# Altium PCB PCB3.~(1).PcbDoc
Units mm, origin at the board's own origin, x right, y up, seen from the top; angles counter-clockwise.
Board outline 57 x 32 mm, 2 copper layers (Top Layer, Bottom Layer); 104 components, 100 nets, 208 pads, 56 vias.
Unrouted connection lines stored in the file: 18.
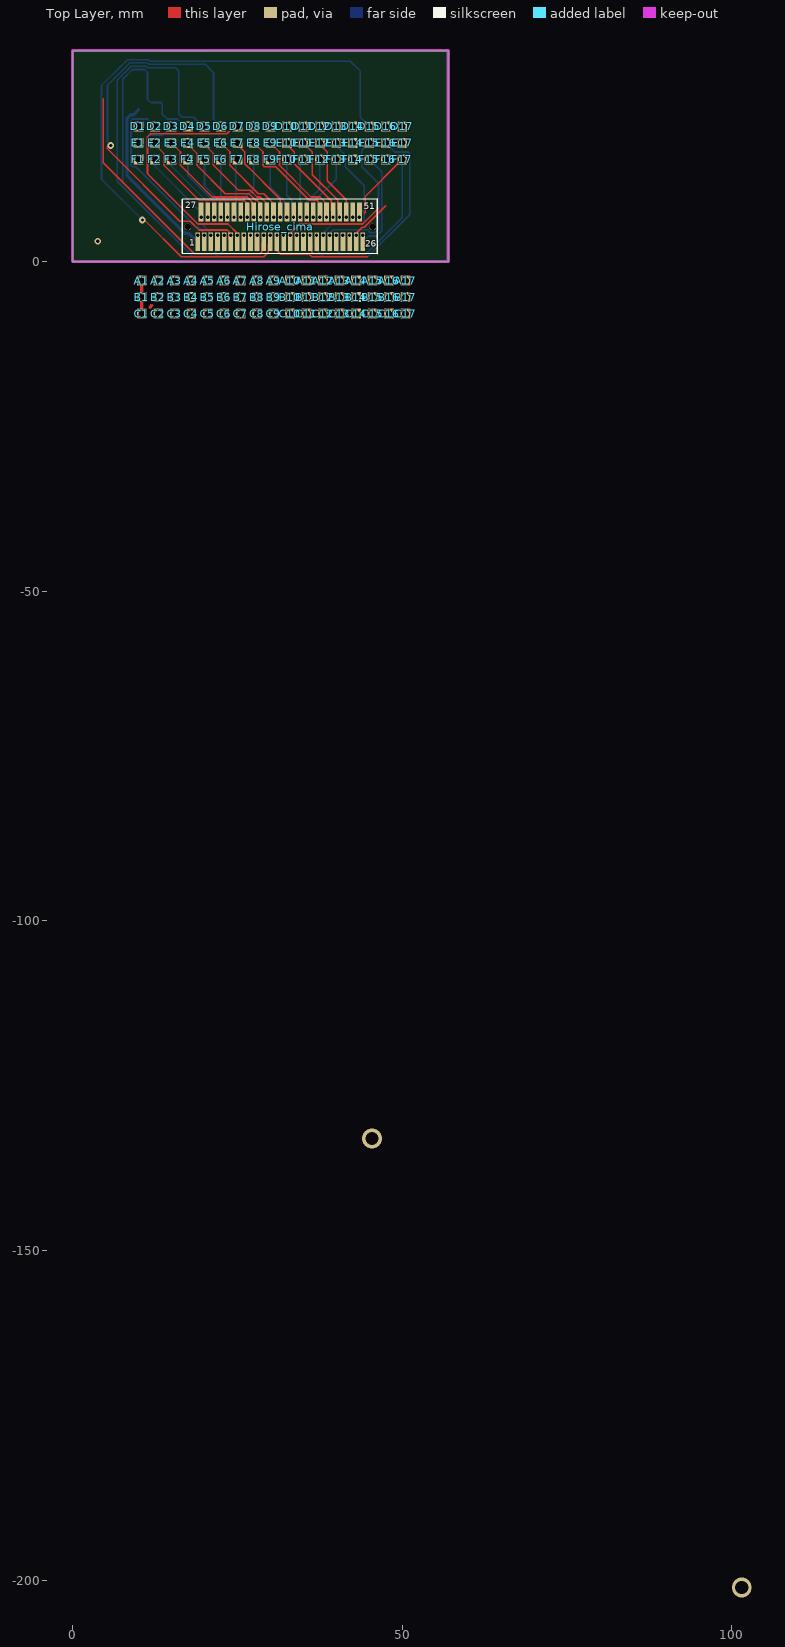
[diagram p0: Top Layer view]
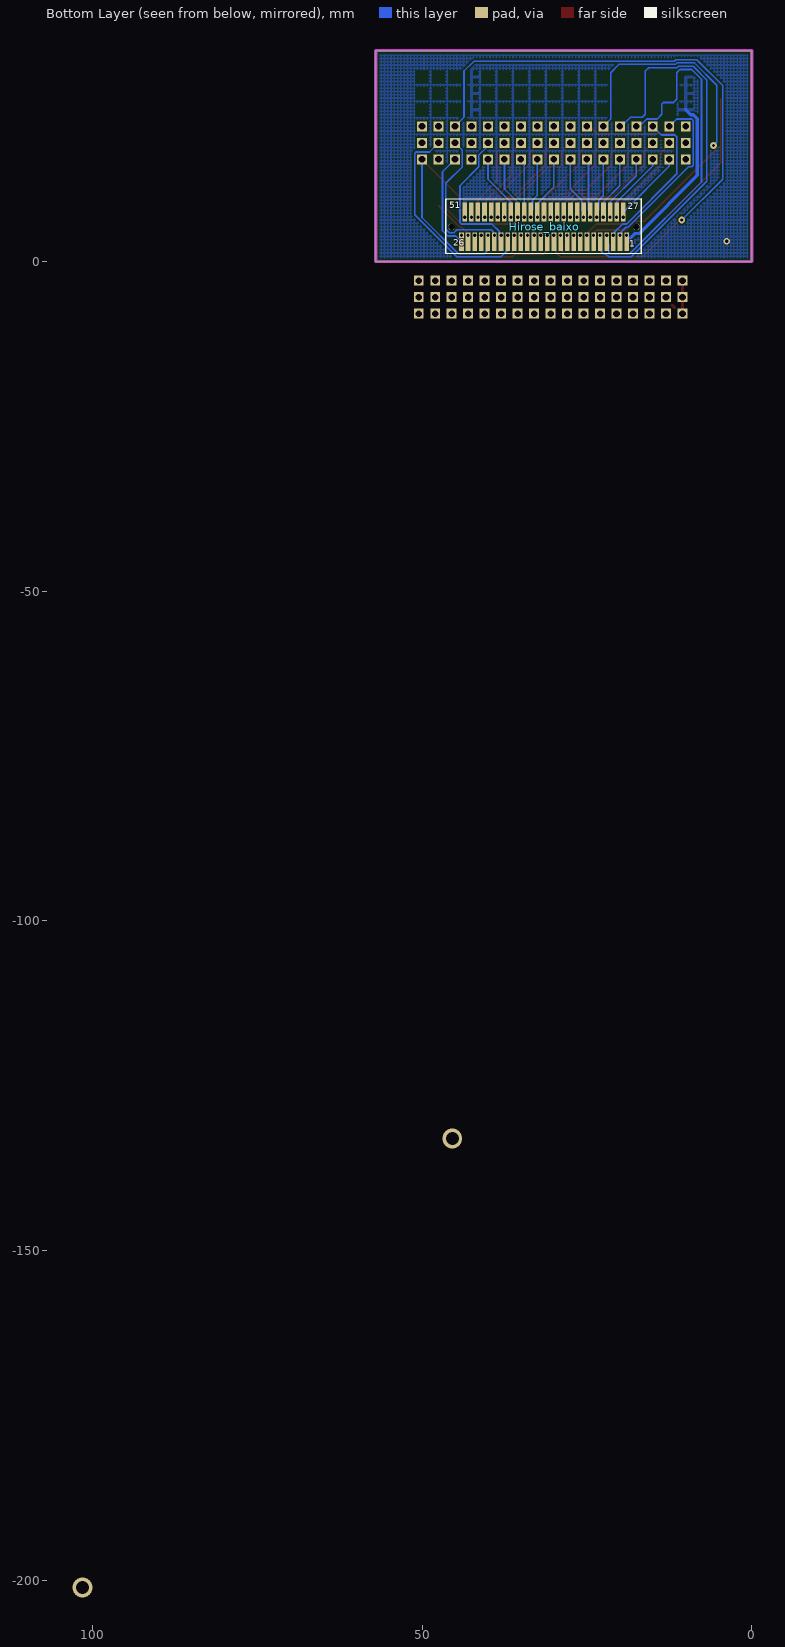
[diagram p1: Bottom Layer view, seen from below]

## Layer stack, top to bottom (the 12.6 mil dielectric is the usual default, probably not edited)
Top Layer: signal copper 0.0356
Dielectric: dielectric 0.32, FR-4, Dk 4.8
Bottom Layer: signal copper 0.0356

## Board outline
0,0 57,0 57,32 0,32

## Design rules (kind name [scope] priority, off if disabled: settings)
Clearance [All] p1: gap=0.25
FabricationTestpoint [(IsPad And (OnTopLayer Or OnBottomLayer))] p1: side=3 testpointundercomponent=TRUE minsize=1.016 maxsize=2.54 preferedsize=1.524 minholesize=0 maxholesize=1.016 preferedholesize=0.813 testpointgrid=0.025 allowsidetop=TRUE allowsidebottom=TRUE usegrid=TRUE gridtolerance=0
PlaneClearance [All] p1: clearance=0.75
PlaneConnect [All] p1: planeconnectstyle=Relief reliefexpansion=0.5 reliefentries=4 reliefconductorwidth=0.5 reliefairgap=0.5
PolygonConnect [All] p1: connectstyle=Relief reliefconductorwidth=0.5 reliefentries=4 polygonreliefangle="90 Angle"
RoutingVias [All] p1: holewidth=0.5 width=1 viastyle="Through Hole" minholewidth=0.711 minwidth=1.27 maxholewidth=0.711 maxwidth=1.27
SilkscreenOverComponentPads [All] p1: minsilkscreentomaskgap=0.254
SolderMaskExpansion [All] p1: expansion=0
Width Alim [(InNet('VCC') OR InNet('GND'))] p1: maxlimit=0.5 minlimit=0.5 preferedwidth=0.5 minimp=50.000000 maximp=50.000000 favimp=50.000000
Width [All] p2: maxlimit=0.25 minlimit=0.25 preferedwidth=0.25 minimp=50.000000 maximp=50.000000 favimp=50.000000
24 further rules are at their usual default settings.

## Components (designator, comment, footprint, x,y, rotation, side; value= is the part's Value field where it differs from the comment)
A1 "buraco" PCBComponent_1 10.5,-2.9 r0 top
A2 "buraco" PCBComponent_1 13,-2.9 r0 top
A3 "buraco" PCBComponent_1 15.5,-2.9 r0 top
A4 "buraco" PCBComponent_1 18,-2.9 r0 top
A5 "buraco" PCBComponent_1 20.5,-2.9 r0 top
A6 "buraco" PCBComponent_1 23,-2.9 r0 top
A7 "buraco" PCBComponent_1 25.5,-2.9 r0 top
A8 "buraco" PCBComponent_1 28,-2.9 r0 top
A9 "buraco" PCBComponent_1 30.5,-2.9 r0 top
A10 "buraco" PCBComponent_1 33,-2.9 r90 top
A11 "buraco" PCBComponent_1 35.5,-2.9 r0 top
A12 "buraco" PCBComponent_1 38,-2.9 r90 top
A13 "buraco" PCBComponent_1 40.5,-2.9 r90 top
A14 "buraco" PCBComponent_1 43,-2.9 r90 top
A15 "buraco" PCBComponent_1 45.5,-2.9 r90 top
A16 "buraco" PCBComponent_1 48,-2.9 r90 top
A17 "buraco" PCBComponent_1 50.5,-2.9 r90 top
B1 "buraco" PCBComponent_1 10.5,-5.4 r0 top
B2 "buraco" PCBComponent_1 13,-5.4 r0 top
B3 "buraco" PCBComponent_1 15.5,-5.4 r0 top
B4 "buraco" PCBComponent_1 18,-5.4 r0 top
B5 "buraco" PCBComponent_1 20.5,-5.4 r0 top
B6 "buraco" PCBComponent_1 23,-5.4 r0 top
B7 "buraco" PCBComponent_1 25.5,-5.4 r0 top
B8 "buraco" PCBComponent_1 28,-5.4 r0 top
B9 "buraco" PCBComponent_1 30.5,-5.4 r0 top
B10 "buraco" PCBComponent_1 33,-5.4 r90 top
B11 "buraco" PCBComponent_1 35.5,-5.4 r0 top
B12 "buraco" PCBComponent_1 38,-5.4 r90 top
B13 "buraco" PCBComponent_1 40.5,-5.4 r90 top
B14 "buraco" PCBComponent_1 43,-5.4 r90 top
B15 "buraco" PCBComponent_1 45.5,-5.4 r90 top
B16 "buraco" PCBComponent_1 48,-5.4 r90 top
B17 "buraco" PCBComponent_1 50.5,-5.4 r90 top
C1 "buraco" PCBComponent_1 10.5,-7.9 r0 top
C2 "buraco" PCBComponent_1 13,-7.9 r0 top
C3 "buraco" PCBComponent_1 15.5,-7.9 r0 top
C4 "buraco" PCBComponent_1 18,-7.9 r0 top
C5 "buraco" PCBComponent_1 20.5,-7.9 r0 top
C6 "buraco" PCBComponent_1 23,-7.9 r0 top
C7 "buraco" PCBComponent_1 25.5,-7.9 r0 top
C8 "buraco" PCBComponent_1 28,-7.9 r0 top
C9 "buraco" PCBComponent_1 30.5,-7.9 r0 top
C10 "buraco" PCBComponent_1 33,-7.9 r90 top
C11 "buraco" PCBComponent_1 35.5,-7.9 r0 top
C12 "buraco" PCBComponent_1 38,-7.9 r90 top
C13 "buraco" PCBComponent_1 40.5,-7.9 r90 top
C14 "buraco" PCBComponent_1 43,-7.9 r90 top
C15 "buraco" PCBComponent_1 45.5,-7.9 r90 top
C16 "buraco" PCBComponent_1 48,-7.9 r90 top
C17 "buraco" PCBComponent_1 50.5,-7.9 r90 top
D1 "buraco" PCBComponent_1 10,20.5 r0 top
D2 "buraco" PCBComponent_1 12.5,20.5 r0 top
D3 "buraco" PCBComponent_1 15,20.5 r0 top
D4 "buraco" PCBComponent_1 17.5,20.5 r0 top
D5 "buraco" PCBComponent_1 20,20.5 r0 top
D6 "buraco" PCBComponent_1 22.5,20.5 r0 top
D7 "buraco" PCBComponent_1 25,20.5 r0 top
D8 "buraco" PCBComponent_1 27.5,20.5 r0 top
D9 "buraco" PCBComponent_1 30,20.5 r0 top
D10 "buraco" PCBComponent_1 32.5,20.5 r90 top
D11 "buraco" PCBComponent_1 35,20.5 r0 top
D12 "buraco" PCBComponent_1 37.5,20.5 r90 top
D13 "buraco" PCBComponent_1 40,20.5 r90 top
D14 "buraco" PCBComponent_1 42.5,20.5 r90 top
D15 "buraco" PCBComponent_1 45,20.5 r90 top
D16 "buraco" PCBComponent_1 47.5,20.5 r90 top
D17 "buraco" PCBComponent_1 50,20.5 r90 top
E1 "buraco" PCBComponent_1 10,18 r0 top
E2 "buraco" PCBComponent_1 12.5,18 r0 top
E3 "buraco" PCBComponent_1 15,18 r0 top
E4 "buraco" PCBComponent_1 17.5,18 r0 top
E5 "buraco" PCBComponent_1 20,18 r0 top
E6 "buraco" PCBComponent_1 22.5,18 r0 top
E7 "buraco" PCBComponent_1 25,18 r0 top
E8 "buraco" PCBComponent_1 27.5,18 r0 top
E9 "buraco" PCBComponent_1 30,18 r0 top
E10 "buraco" PCBComponent_1 32.5,18 r90 top
E11 "buraco" PCBComponent_1 35,18 r0 top
E12 "buraco" PCBComponent_1 37.5,18 r90 top
E13 "buraco" PCBComponent_1 40,18 r90 top
E14 "buraco" PCBComponent_1 42.5,18 r90 top
E15 "buraco" PCBComponent_1 45,18 r90 top
E16 "buraco" PCBComponent_1 47.5,18 r90 top
E17 "buraco" PCBComponent_1 50,18 r90 top
F1 "buraco" PCBComponent_1 10,15.5 r0 top
F2 "buraco" PCBComponent_1 12.5,15.5 r0 top
F3 "buraco" PCBComponent_1 15,15.5 r0 top
F4 "buraco" PCBComponent_1 17.5,15.5 r0 top
F5 "buraco" PCBComponent_1 20,15.5 r0 top
F6 "buraco" PCBComponent_1 22.5,15.5 r0 top
F7 "buraco" PCBComponent_1 25,15.5 r0 top
F8 "buraco" PCBComponent_1 27.5,15.5 r0 top
F9 "buraco" PCBComponent_1 30,15.5 r0 top
F10 "buraco" PCBComponent_1 32.5,15.5 r90 top
F11 "buraco" PCBComponent_1 35,15.5 r0 top
F12 "buraco" PCBComponent_1 37.5,15.5 r90 top
F13 "buraco" PCBComponent_1 40,15.5 r90 top
F14 "buraco" PCBComponent_1 42.5,15.5 r90 top
F15 "buraco" PCBComponent_1 45,15.5 r90 top
F16 "buraco" PCBComponent_1 47.5,15.5 r90 top
F17 "buraco" PCBComponent_1 50,15.5 r90 top
Hirose_baixo "Hirose" "hirose - baixo" 31.5,7.5 r180 bottom
Hirose_cima "Hirose" hirose 31.5,7.5 r0 top

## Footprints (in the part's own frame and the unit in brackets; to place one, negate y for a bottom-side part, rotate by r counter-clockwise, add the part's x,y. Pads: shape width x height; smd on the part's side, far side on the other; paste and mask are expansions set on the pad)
hirose [mm] "hirose"
  round 1 hole 1: 0(-14.02,-2.25) 0(14.02,-2.25)
  rect 0.7x2.84 smd: 1(-12.52,-4.5) 2(-11.52,-4.5) 3(-10.52,-4.5) 4(-9.52,-4.5) 5(-8.52,-4.5) 6(-7.52,-4.5) 7(-6.52,-4.5) 8(-5.52,-4.5) 9(-4.52,-4.5) 10(-3.52,-4.5) 11(-2.52,-4.5) 12(-1.52,-4.5) 13(-0.51,-4.5) 14(0.51,-4.5) 15(1.52,-4.5) 16(2.52,-4.5) 17(3.52,-4.5) 18(4.52,-4.5) 19(5.52,-4.5) 20(6.52,-4.5) 21(7.52,-4.5) 22(8.52,-4.5) 23(9.52,-4.5) 24(10.52,-4.5) 25(11.52,-4.5) 26(12.52,-4.5) 27(-12.02,0) 28(-11.02,0) 29(-10.02,0) 30(-9.02,0) 31(-8.02,0) 32(-7.02,0) 33(-6.02,0) 34(-5.02,0) 35(-4.02,0) 36(-3.02,0) 37(-2.02,0) 38(-1.02,0) 39(0,0) 40(1.02,0) 41(2.02,0) 42(3.02,0) 43(4.02,0) 44(5.02,0) 45(6.02,0) 46(7.02,0) 47(8.02,0) 48(9.02,0) 49(10.02,0) 50(11.02,0) 51(12.02,0)
  silkscreen extent -14.9,-6.35 14.73,2
"hirose - baixo" [mm] "hirose"
  round 1 hole 1: 0(-14.02,-2.25) 0(14.02,-2.25)
  rect 0.7x2.84 smd: 1(12.52,-4.5) 2(11.52,-4.5) 3(10.52,-4.5) 4(9.52,-4.5) 5(8.52,-4.5) 6(7.52,-4.5) 7(6.52,-4.5) 8(5.52,-4.5) 9(4.52,-4.5) 10(3.52,-4.5) 11(2.52,-4.5) 12(1.52,-4.5) 13(0.51,-4.5) 14(-0.51,-4.5) 15(-1.52,-4.5) 16(-2.52,-4.5) 17(-3.52,-4.5) 18(-4.52,-4.5) 19(-5.52,-4.5) 20(-6.52,-4.5) 21(-7.52,-4.5) 22(-8.52,-4.5) 23(-9.52,-4.5) 24(-10.52,-4.5) 25(-11.52,-4.5) 26(-12.52,-4.5) 27(12.02,0) 28(11.02,0) 29(10.02,0) 30(9.02,0) 31(8.02,0) 32(7.02,0) 33(6.02,0) 34(5.02,0) 35(4.02,0) 36(3.02,0) 37(2.02,0) 38(1.02,0) 39(0,0) 40(-1.02,0) 41(-2.02,0) 42(-3.02,0) 43(-4.02,0) 44(-5.02,0) 45(-6.02,0) 46(-7.02,0) 47(-8.02,0) 48(-9.02,0) 49(-10.02,0) 50(-11.02,0) 51(-12.02,0)
  silkscreen extent -14.9,-6.35 14.72,2
PCBComponent_1 [mm]
  rect 1.5x1.5 hole 1: 1(0,0)

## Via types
v1: diameter 0.5, hole 0.5, Top Layer to Bottom Layer, 50 vias
v2: diameter 1, hole 0.5, Top Layer to Bottom Layer, 3 vias
v3: diameter 3, hole 2, Top Layer to Bottom Layer, 2 vias
v4: diameter 0.6, hole 0.5, Top Layer to Bottom Layer, 1 vias

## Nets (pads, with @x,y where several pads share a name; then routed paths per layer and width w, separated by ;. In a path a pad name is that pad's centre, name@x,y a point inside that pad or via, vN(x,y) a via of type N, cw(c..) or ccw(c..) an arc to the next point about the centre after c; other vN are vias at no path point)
A2: A2.1
A3: A3.1
A4: A4.1
A5: A5.1
A6: A6.1
A7: A7.1
A8: A8.1
A9: A9.1
A10: A10.1
A11: A11.1
A12: A12.1
A13: A13.1
A15: A15.1
A16: A16.1
A17: A17.1
AIR1: Hirose_baixo.8 Hirose_cima.8
  other v1: 26,4
AIR2: Hirose_baixo.9 Hirose_cima.9
  other v1: 27,4
AIR3: Hirose_baixo.10 Hirose_cima.10
  other v1: 28,4
AIR4: Hirose_baixo.14 Hirose_cima.14
  other v1: 32,4
AIR5: Hirose_baixo.16 Hirose_cima.16
  other v1: 34,4
AIR6: Hirose_baixo.17 Hirose_cima.17
  other v1: 35,4
AIR7: Hirose_baixo.23 Hirose_cima.23
  other v1: 41,4
AIR8: Hirose_baixo.24 Hirose_cima.24
  other v1: 42,4
B2: B2.1
B3: B3.1
B4: B4.1
B5: B5.1
B6: B6.1
B7: B7.1
B8: B8.1
B9: B9.1
B10: B10.1
B11: B11.1
B12: B12.1
B13: B13.1
B15: B15.1
B16: B16.1
B17: B17.1
C2: C2.1
C3: C3.1
C4: C4.1
C5: C5.1
C6: C6.1
C7: C7.1
C8: C8.1
C9: C9.1
C10: C10.1
C11: C11.1
C12: C12.1
C13: C13.1
C15: C15.1
C16: C16.1
C17: C17.1 Hirose_baixo.11 Hirose_cima.11 | length 41.2
  Top Layer w0.25: 4.675,24.705 4.675,15.005 18.475,1.205 28.485,1.205 28.705,1.425 28.705,2.725 Hirose_cima.11
  other v1: 29,4
D2: D2.1 Hirose_baixo.2 Hirose_cima.2 | length 27.7
  Bottom Layer w0.25: D2.1 11.375,21.625 9.095,21.625 8.875,21.405 8.875,14.595 9.095,14.375 9.598,14.375 18.773,5.2 19.08,5.2 19.98,4.3 Hirose_baixo.2
  other v1: 19.98,4
D3: D3.1 Hirose_baixo.3 Hirose_cima.3 | length 24.5
  Bottom Layer w0.25: D3.1 13.7,19.2 11.67,19.2 11.375,18.905 11.375,13.305 18.975,5.705 19.575,5.705 20.98,4.3 Hirose_baixo.3
  other v1: 20.98,4
D4: D4.1 Hirose_baixo.4 Hirose_cima.4 | length 53.3
  Bottom Layer w0.25: D4.1 17.03,20.5 15.905,21.625 14.345,21.625 13.625,22.345 13.625,23.905 13.405,24.125 11.845,24.125 11.375,24.595 11.375,28.655 10.905,29.125 9.095,29.125 7.625,27.655 7.625,12.055 18.475,1.205 21.485,1.205 21.705,1.425 21.705,2.725 Hirose_baixo.4
  other v1: 22,4
D5: D5.1 Hirose_baixo.5 Hirose_cima.5 | length 59.7
  Bottom Layer w0.25: D5.1 19.763,20.5 18.388,21.875 16.595,21.875 16.125,22.345 16.125,28.905 15.63,29.4 11.337,29.4 11.112,29.625 8.888,29.625 6.8,27.537 6.8,12.173 18.268,0.705 21.692,0.705 22.192,1.205 22.485,1.205 22.98,1.7 Hirose_baixo.5
  other v1: 23,4
D6: D6.1 Hirose_baixo.6 Hirose_cima.6 | length 62.3
  Top Layer w0.25: v2(5.8,17.6) 5.4,17.6 5.3,17.5 5.3,17.1 16.275,6.125 17.848,6.125 19.178,4.795 23.485,4.795 23.705,4.575 23.705,3.275 Hirose_cima.6
  Bottom Layer w0.25: v2(5.8,17.6) 5.3,18.1 5.3,26.745 8.68,30.125 11.32,30.125 11.545,29.9 20.13,29.9 21.375,28.655 21.375,21.625 D6.1
  other v1: 24,4
D7: D7.1 Hirose_baixo.7 Hirose_cima.7 | length 38.5
  Top Layer w0.25: Hirose_cima.7 24.98,4.3 23.575,5.705 18.975,5.705 11.375,13.305 11.375,18.905 11.845,19.375 23.405,19.375 24.53,20.5 D7.1
  other v1: 25,4
D8: D8.1
D9: D9.1
D10: D10.1
D11: D11.1
D12: D12.1
D13: D13.1
D15: D15.1 Hirose_baixo.12 Hirose_cima.12 | length 96.9
  Top Layer w0.25: v2(10.6,6.3) 10.9,6.3 16.495,0.705 28.985,0.705 29.705,1.425 29.705,2.725 Hirose_cima.12
  Bottom Layer w0.25: v2(10.6,6.3) 4.4,12.5 4.4,26.7 8.325,30.625 11.527,30.625 11.752,30.4 42.13,30.4 43.625,28.905 43.625,21.875 D15.1
  other v1: 30,4
D16: D16.1 Hirose_baixo.13 Hirose_cima.13 | length 15.4
  Top Layer w0.25: Hirose_cima.13 30.99,1.72 31.585,1.125 35.888,1.125 36.308,0.705 44.732,0.705
  other v1: 31,4
D17: D17.1 Hirose_baixo.15 Hirose_cima.15 | length 16.2
  Top Layer w0.25: Hirose_cima.15 33.02,4.3 34.425,5.705 44.025,5.705 46.375,8.055
  other v1: 33,4
E2: E2.1 Hirose_baixo.34 Hirose_cima.34 | length 20.3
  Top Layer w0.25: E2.1 12.5,17.75 13.875,16.375 13.875,14.595 19.175,9.295 25.985,9.295 26.48,8.8 Hirose_cima.34
  other v1: 26.5,6.7
E3: E3.1 Hirose_baixo.35 Hirose_cima.35 | length 18.8
  Top Layer w0.25: E3.1 16.375,16.625 16.375,14.595 21.175,9.795 26.485,9.795 27.205,9.075 27.205,7.775 Hirose_cima.35
  other v1: 27.5,6.7
E4: E4.1 Hirose_baixo.36 Hirose_cima.36 | length 17.3
  Top Layer w0.25: E4.1 17.5,17.75 18.875,16.375 18.875,14.595 23.175,10.295 26.76,10.295 27.76,9.295 27.985,9.295 28.48,8.8 Hirose_cima.36
  other v1: 28.5,6.7
E5: E5.1 Hirose_baixo.37 Hirose_cima.37 | length 15.8
  Top Layer w0.25: E5.1 20,17.75 21.375,16.375 21.375,14.595 25.175,10.795 26.968,10.795 27.968,9.795 28.485,9.795 29.48,8.8 Hirose_cima.37
  other v1: 29.5,6.7
E6: E6.1 Hirose_baixo.38 Hirose_cima.38 | length 14.3
  Top Layer w0.25: E6.1 23.875,16.625 23.875,14.595 28.175,10.295 28.985,10.295 30.48,8.8 Hirose_cima.38
  other v1: 30.5,6.7
E7: E7.1 Hirose_baixo.39 Hirose_cima.39 | length 13.2
  Top Layer w0.25: E7.1 25,17.75 26.125,16.625 26.125,14.845 27.469,13.501 30.156,10.813 31.5,9.47 Hirose_cima.39
  other v1: 31.5,6.7
E8: E8.1 Hirose_baixo.45 Hirose_cima.45 | length 16.3
  Top Layer w0.25: E8.1 28.875,16.625 28.875,14.595 29.095,14.375 30.825,14.375 35.905,9.295 37.025,9.295 37.52,8.8 Hirose_cima.45
  other v1: 37.5,6.7
E9: E9.1 Hirose_baixo.46 Hirose_cima.46 | length 14.8
  Top Layer w0.25: E9.1 31.375,16.625 31.375,14.595 36.175,9.795 37.525,9.795 38.52,8.8 Hirose_cima.46
  other v1: 38.5,6.7
E10: E10.1 Hirose_baixo.47 Hirose_cima.47 | length 13.4
  Top Layer w0.25: E10.1 32.5,17.75 33.625,16.625 33.625,14.845 39.245,9.225 39.245,7.775 Hirose_cima.47
  other v1: 39.5,6.7
E11: E11.1 Hirose_baixo.48 Hirose_cima.48 | length 12.8
  Top Layer w0.25: E11.1 36.375,16.625 36.375,13.165 40.245,9.295 40.245,7.775 Hirose_cima.48
  other v1: 40.5,6.7
E12: E12.1 Hirose_baixo.49 Hirose_cima.49 | length 12.2
  Top Layer w0.25: E12.1 37.5,17.75 38.625,16.625 38.625,12.275 41.52,9.38 Hirose_cima.49
  other v1: 41.5,6.7
E13: E13.1 Hirose_baixo.20 Hirose_cima.20 | length 22
  Bottom Layer w0.25: Hirose_baixo.20 38.295,3.275 38.295,4.575 39.425,5.705 44.025,5.705 44.245,5.925 44.245,11.505 41.375,14.375 41.375,16.155 40,17.53 E13.1
  other v1: 38,4
E15: E15.1 Hirose_baixo.21 Hirose_cima.21 | length 23.9
  Bottom Layer w0.25: Hirose_baixo.21 39.02,4.3 39.52,4.8 44.732,4.8 45.158,4.375 45.882,4.375 46.395,4.888 46.395,11.855 43.875,14.375 43.875,16.875 E15.1
  other v1: 39.02,4
E16: E16.1 Hirose_baixo.19 Hirose_cima.19 | length 30.8
  Bottom Layer w0.25: Hirose_baixo.19@37.02,1.7 38.015,0.705 44.732,0.705 51.125,7.098 51.125,16.405 50.905,16.625 48.875,16.625 E16.1
  other v1: 37,4
E17: E17.1 Hirose_baixo.18 Hirose_cima.18 | length 10.5
  Top Layer w0.25: Hirose_cima.18 36.295,2.725 36.295,1.425 36.515,1.205 44.525,1.205 ; E17.1@50,17.53 E17.1
  other v1: 36,4
F2: F2.1 Hirose_baixo.27 Hirose_cima.27 | length 10.9
  Bottom Layer w0.25: F2.1 12.5,14.48 Hirose_baixo.27
  other v4: 19.5,6.7
F3: F3.1 Hirose_baixo.28 Hirose_cima.28 | length 10.3
  Bottom Layer w0.25: F3.1 15,14.5 20.48,9.02 Hirose_baixo.28
  other v1: 20.5,6.7
F4: F4.1 Hirose_baixo.29 Hirose_cima.29 | length 9.6
  Bottom Layer w0.25: F4.1 17.5,13 21.48,9.02 Hirose_baixo.29
  other v1: 21.5,6.7
F5: F5.1 Hirose_baixo.30 Hirose_cima.30 | length 9
  Bottom Layer w0.25: F5.1 20,11.5 22.48,9.02 Hirose_baixo.30
  other v1: 22.5,6.7
F6: F6.1 Hirose_baixo.31 Hirose_cima.31 | length 8
  Bottom Layer w0.25: F6.1 22.5,10 23.205,9.295 Hirose_baixo.31@23.205,7.775
  other v1: 23.5,6.7
F7: F7.1 Hirose_baixo.32 Hirose_cima.32 | length 8.2
  Bottom Layer w0.25: Hirose_baixo.32 24.755,7.775 24.755,15.255 F7.1
  other v1: 24.5,6.7
F8: F8.1 Hirose_baixo.33 Hirose_cima.33 | length 8.8
  Bottom Layer w0.25: Hirose_baixo.33 25.755,7.775 25.755,9.295 27.5,11.04 F8.1
  other v1: 25.5,6.7
F9: F9.1 Hirose_baixo.40 Hirose_cima.40 | length 9
  Bottom Layer w0.25: F9.1 30,11.3 32.52,8.78 Hirose_baixo.40
  other v1: 32.5,6.7
F10: F10.1 Hirose_baixo.41 Hirose_cima.41 | length 8.4
  Bottom Layer w0.25: F10.1 32.5,10.04 33.245,9.295 33.245,7.775 Hirose_baixo.41
  other v1: 33.5,6.7
F11: F11.1 Hirose_baixo.42 Hirose_cima.42 | length 8.2
  Bottom Layer w0.25: Hirose_baixo.42 34.52,15.02 F11.1
  other v1: 34.5,6.7
F12: F12.1 Hirose_baixo.43 Hirose_cima.43 | length 8.8
  Bottom Layer w0.25: Hirose_baixo.43 35.52,9.02 37.5,11 F12.1
  other v1: 35.5,6.7
F13: F13.1 Hirose_baixo.44 Hirose_cima.44 | length 9.4
  Bottom Layer w0.25: Hirose_baixo.44 36.52,9.02 40,12.5 F13.1
  other v1: 36.5,6.7
F15: F15.1 Hirose_baixo.26 Hirose_cima.26 | length 15.2
  Bottom Layer w0.25: Hirose_baixo.26 44.895,3.875 46.09,3.875 46.895,4.68 46.895,13.605 F15.1
  other v1: 44,4
F16: F16.1 Hirose_baixo.25 Hirose_cima.25 | length 8.8
  Top Layer w0.25: Hirose_cima.25 43.02,4.3 43.925,5.205 44.232,5.205 47.5,8.473
  Bottom Layer w0.25: Hirose_baixo.25 Hirose_baixo.25@43.02,4.3
  other v1: 43.02,4
F17: F17.1 Hirose_baixo.22 Hirose_cima.22 | length 33.1
  Top Layer w0.25: 44.245,7.341 44.375,7.471 44.375,9.875 F17.1
  Bottom Layer w0.25: Hirose_baixo.22 40.02,1.7 40.515,1.205 44.525,1.205 50,6.68 F17.1
  other v1: 40,4
GND: A1.1 A14.1 B1.1 B14.1 C1.1 C14.1 Hirose_baixo.1 Hirose_baixo.51 Hirose_cima.1 Hirose_cima.51 | length 31.1
  Top Layer w0.5: C1.1 B1.1 A1.1 ; Hirose_cima.51 Hirose_cima.51@43.75,7.73
  Bottom Layer w0.5: 10,23 9.25,22.25 8.836,22.25 8.25,21.664 8.25,13.066 17.066,4.25 17.73,4.25 Hirose_baixo.1
  other v1: 19,4 43.5,6.7
  other v2: 3.8,3.1
VCC: D1.1 D14.1 E1.1 E14.1 F1.1 F14.1 Hirose_baixo.50 Hirose_cima.50 | length 0.7
  Top Layer w0.5: 11.75,-6.943 12.043,-6.65 ; D14.1@42.207,20.5 D14.1
  other v1: 42.5,6.7
pads on no net: Hirose_baixo.0 Hirose_cima.0
copper on no net:
  other v3: 101.5,-201.1 45.4,-133

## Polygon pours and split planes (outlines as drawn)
GND on Bottom Layer "pmassa-cima" (hatched 90Degree grid 0.5 track 0.25, remove dead copper, pour order 4): -0.1,0 0.1,0.2 0.1,32 57,32 57.1,31.9 56.9,31.7 56.9,0

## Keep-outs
Keep-Out Layer:
  the board outline again, w0.5

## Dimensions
0,0 to 0,32 on Mechanical 1
0,0 to 57,0 on Mechanical 1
